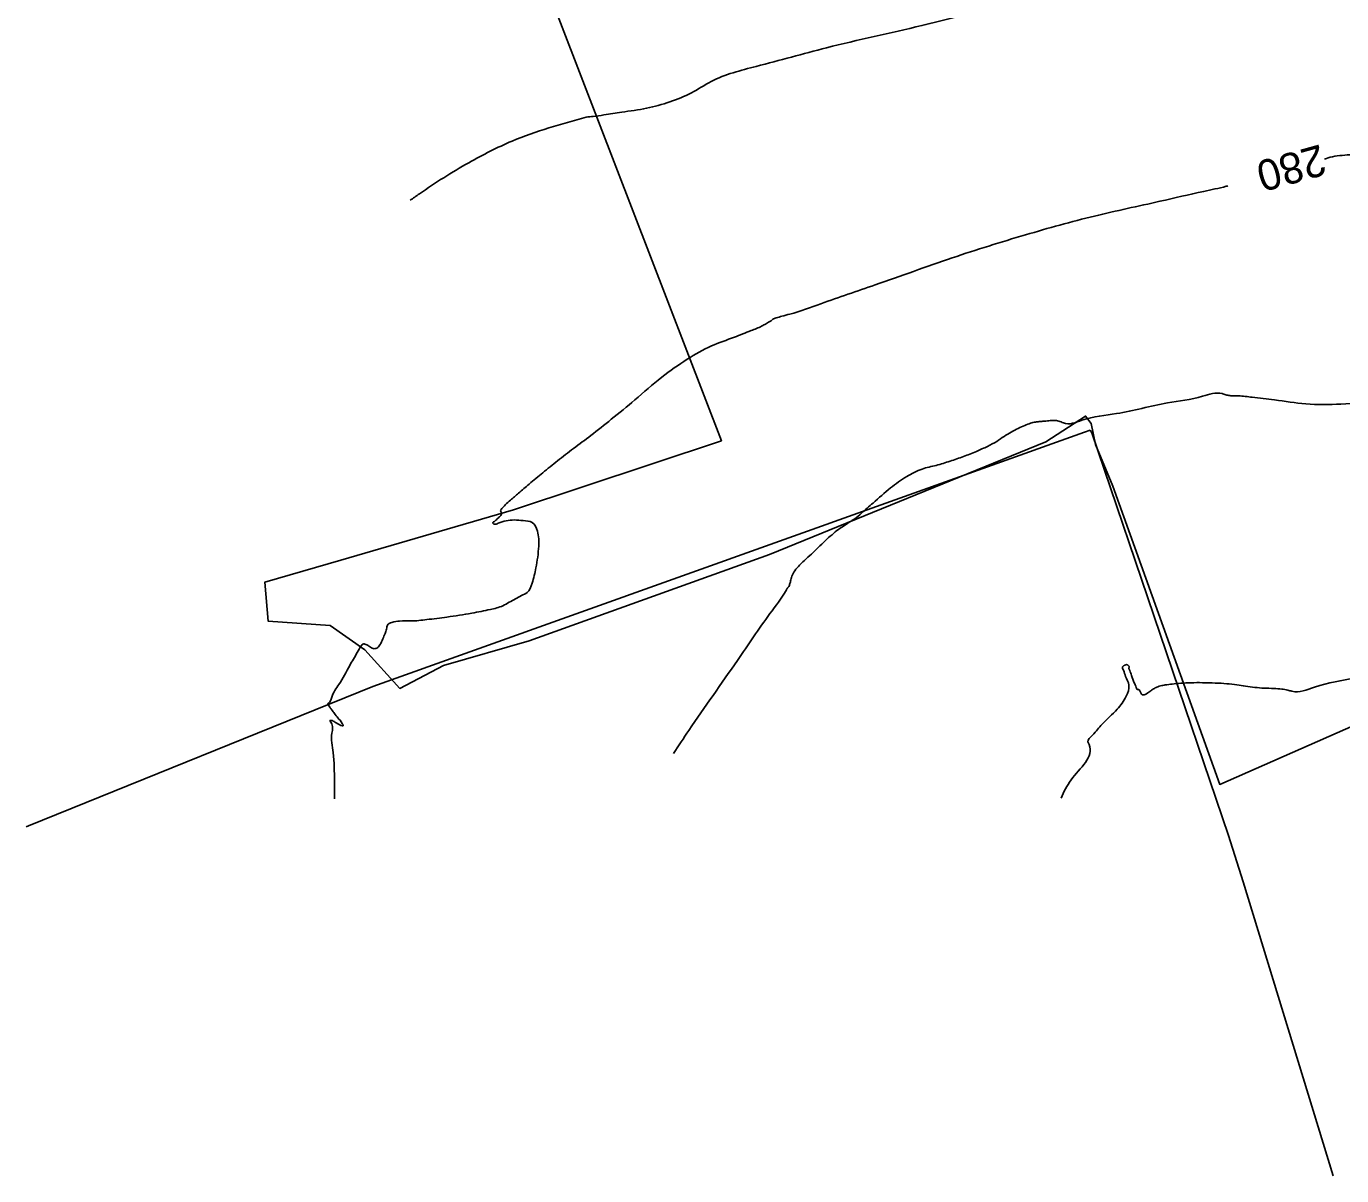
# Model space of a CAD drawing. Extents: x -478464 to -472469, y -1120963 to -1113785.
# Drawn here: x -475889.9 to -475719.4, y -1116153.7 to -1116004.7 of the extents above; entities that cross this region are included whole.
import ezdxf

# ---------------------------------------------------------------- set-up
doc = ezdxf.new("R2010")
doc.units = 0
for name, color, linetype in [('ObPÚ', 7, 'Continuous'), ('VAK_vodovod', 7, 'Continuous'), ('Vrstevnice_hlavni', 7, 'Continuous'), ('Vrstevnice_popis', 7, 'Continuous'), ('Vrstevnice_vedlejsi', 7, 'Continuous')]:
    doc.layers.add(name, color=color, linetype=linetype)

msp = doc.modelspace()

# ---------------------------------------------------------------- linework, layer by layer
at = {"layer": 'ObPÚ'}
msp.add_lwpolyline([(-475822.67, -1115998.95), (-475799.8, -1116058.43), (-475826.72, -1116067.41), (-475849.13, -1116073.91), (-475858.96, -1116076.76), (-475858.53, -1116081.84), (-475850.51, -1116082.37), (-475846.01, -1116085.52), (-475841.49, -1116090.53), (-475835.81, -1116087.59), (-475824.69, -1116084.35), (-475793.58, -1116073.18), (-475757.75, -1116058.57), (-475752.61, -1116055.25), (-475751.89, -1116056.2), (-475751.3, -1116058.92), (-475749.06, -1116064.34), (-475735.22, -1116102.98), (-475699.02, -1116087.04)], dxfattribs=at)
at = {"layer": 'VAK_vodovod'}
for points in [[(-475889.88, -1116108.469), (-475889.59, -1116108.35), (-475844.989, -1116090.309), (-475752.719, -1116057.309), (-475752.027, -1116057.077)], [(-475752.027, -1116057.077), (-475751.789, -1116057.42), (-475734.09, -1116109.6), (-475732.17, -1116115.59), (-475720.526, -1116153.696)]]:
    msp.add_lwpolyline(points, dxfattribs=at)
at = {"layer": 'Vrstevnice_hlavni'}
for points in [[(-475721.656, -1116021.921), (-475720.62, -1116021.633), (-475718.031, -1116021.363), (-475713.372, -1116020.965), (-475706.644, -1116020.44), (-475699.945, -1116019.714), (-475693.277, -1116018.786), (-475686.638, -1116017.656), (-475681.664, -1116016.951), (-475678.354, -1116016.672), (-475676.708, -1116016.818), (-475672.839, -1116016.975), (-475666.748, -1116017.142), (-475658.434, -1116017.321), (-475652.719, -1116017.574), (-475649.603, -1116017.901), (-475649.085, -1116018.302), (-475648.228, -1116018.475), (-475647.031, -1116018.42), (-475645.495, -1116018.137), (-475643.612, -1116018.247), (-475641.384, -1116018.748), (-475638.81, -1116019.641), (-475635.789, -1116020.801), (-475632.319, -1116022.229), (-475628.402, -1116023.923), (-475624.07, -1116026.55), (-475619.323, -1116030.11), (-475614.162, -1116034.601), (-475609.969, -1116038.094), (-475606.743, -1116040.588), (-475604.485, -1116042.082), (-475602.862, -1116043.199), (-475601.875, -1116043.937), (-475601.523, -1116044.296), (-475601.083, -1116044.742), (-475600.556, -1116045.273), (-475599.94, -1116045.889), (-475598.642, -1116047.373), (-475596.662, -1116049.725), (-475594.001, -1116052.945), (-475592.012, -1116055.361), (-475590.694, -1116056.974), (-475590.049, -1116057.784), (-475589.53, -1116058.403), (-475589.136, -1116058.832), (-475588.867, -1116059.071), (-475588.149, -1116059.767), (-475586.98, -1116060.92), (-475585.362, -1116062.531), (-475583.813, -1116064.295), (-475582.333, -1116066.213), (-475580.922, -1116068.285), (-475581.168, -1116072.263)], [(-475734.144, -1116025.39), (-475734.387, -1116025.457), (-475737.287, -1116026.117), (-475742.967, -1116027.402), (-475751.425, -1116029.313), (-475760.397, -1116031.757), (-475769.883, -1116034.735), (-475779.883, -1116038.248), (-475786.895, -1116040.679), (-475790.919, -1116042.028), (-475791.955, -1116042.297), (-475792.697, -1116042.52), (-475793.144, -1116042.699), (-475793.297, -1116042.833), (-475793.588, -1116043.024), (-475794.017, -1116043.273), (-475794.584, -1116043.58), (-475795.952, -1116044.161), (-475798.119, -1116045.015), (-475801.087, -1116046.144), (-475804.225, -1116047.876), (-475807.532, -1116050.21), (-475811.009, -1116053.146), (-475814.071, -1116055.662), (-475816.718, -1116057.758), (-475818.95, -1116059.434), (-475821.025, -1116061.042), (-475822.943, -1116062.582), (-475824.704, -1116064.055), (-475826.102, -1116065.24), (-475827.136, -1116066.137), (-475827.806, -1116066.746), (-475828.232, -1116067.209), (-475828.413, -1116067.526), (-475828.351, -1116067.695), (-475828.313, -1116067.833), (-475828.301, -1116067.938), (-475828.314, -1116068.011), (-475828.374, -1116068.106), (-475828.48, -1116068.222), (-475828.632, -1116068.36), (-475828.838, -1116068.557), (-475829.097, -1116068.811), (-475829.411, -1116069.123), (-475829.283, -1116069.23), (-475828.713, -1116069.131), (-475827.701, -1116068.826), (-475826.629, -1116068.71), (-475825.498, -1116068.782), (-475824.306, -1116069.042), (-475823.632, -1116070.151), (-475823.476, -1116072.107), (-475823.837, -1116074.911), (-475824.33, -1116076.913), (-475824.954, -1116078.115), (-475825.71, -1116078.516), (-475826.49, -1116078.935), (-475827.294, -1116079.372), (-475828.122, -1116079.828), (-475829.743, -1116080.299), (-475832.155, -1116080.784), (-475835.36, -1116081.285), (-475837.985, -1116081.623), (-475840.031, -1116081.798), (-475841.497, -1116081.812), (-475842.513, -1116081.989), (-475843.078, -1116082.332), (-475843.194, -1116082.84), (-475843.394, -1116083.435), (-475843.681, -1116084.119), (-475844.052, -1116084.891), (-475844.462, -1116085.311), (-475844.911, -1116085.379), (-475845.399, -1116085.096), (-475845.763, -1116084.899), (-475846.004, -1116084.788), (-475846.121, -1116084.764), (-475846.236, -1116084.79), (-475846.348, -1116084.866), (-475846.459, -1116084.992), (-475846.998, -1116085.894), (-475847.966, -1116087.573), (-475849.364, -1116090.027), (-475850.298, -1116091.666), (-475850.771, -1116092.488), (-475850.781, -1116092.494), (-475850.786, -1116092.51), (-475850.787, -1116092.538), (-475850.784, -1116092.577), (-475850.701, -1116092.72), (-475850.538, -1116092.969), (-475850.294, -1116093.322), (-475849.947, -1116093.789), (-475849.495, -1116094.37), (-475848.939, -1116095.066), (-475848.819, -1116095.385), (-475849.137, -1116095.329)], [(-475849.137, -1116095.329), (-475849.892, -1116094.896), (-475850.356, -1116094.685), (-475850.529, -1116094.697), (-475850.411, -1116094.93), (-475850.275, -1116096.32), (-475850.122, -1116098.866), (-475849.952, -1116102.567), (-475849.948, -1116104.864)]]:
    msp.add_spline(points, degree=3, dxfattribs=at)
at = {"layer": 'Vrstevnice_vedlejsi'}
for points in [[(-475635.042, -1115991.631), (-475637.589, -1115991.349), (-475640.452, -1115991.123), (-475643.63, -1115990.953), (-475647.123, -1115990.838), (-475652.644, -1115990.705), (-475660.192, -1115990.553), (-475669.769, -1115990.383), (-475679.613, -1115990.46), (-475689.725, -1115990.784), (-475700.106, -1115991.356), (-475708.103, -1115991.646), (-475713.716, -1115991.655), (-475716.946, -1115991.383), (-475719.838, -1115991.391), (-475722.394, -1115991.679), (-475724.612, -1115992.248), (-475729.232, -1115993.416), (-475736.252, -1115995.184), (-475745.674, -1115997.552), (-475752.388, -1115999.252), (-475756.395, -1116000.282), (-475757.696, -1116000.643), (-475758.674, -1116000.909), (-475759.329, -1116001.079), (-475759.662, -1116001.154), (-475760.046, -1116001.261), (-475760.481, -1116001.4), (-475760.966, -1116001.571), (-475765.411, -1116002.645), (-475773.817, -1116004.623), (-475786.183, -1116007.506), (-475795.284, -1116009.921), (-475801.119, -1116011.87), (-475803.69, -1116013.353), (-475806.479, -1116014.511), (-475809.486, -1116015.345), (-475812.713, -1116015.854), (-475815.017, -1116016.208), (-475816.399, -1116016.406), (-475817.32, -1116016.489)], [(-475817.32, -1116016.489), (-475826.925, -1116019.603), (-475832.531, -1116022.398), (-475838.942, -1116026.432), (-475840.138, -1116027.275)], [(-475700.917, -1116051.306), (-475702.197, -1116051.318), (-475704.886, -1116051.643), (-475708.985, -1116052.28), (-475714.492, -1116053.23), (-475719.518, -1116053.691), (-475724.06, -1116053.664), (-475728.121, -1116053.148), (-475731.025, -1116052.804), (-475732.775, -1116052.632), (-475733.368, -1116052.632), (-475733.923, -1116052.581), (-475734.439, -1116052.479), (-475734.917, -1116052.326), (-475737.433, -1116052.681), (-475741.989, -1116053.543), (-475748.583, -1116054.912), (-475753.08, -1116055.776), (-475755.48, -1116056.133), (-475755.782, -1116055.985), (-475756.085, -1116055.883), (-475756.389, -1116055.827), (-475756.695, -1116055.817), (-475757.021, -1116055.823), (-475757.369, -1116055.843), (-475757.738, -1116055.879), (-475758.15, -1116055.919), (-475758.606, -1116055.963), (-475759.106, -1116056.011), (-475759.727, -1116056.173), (-475760.47, -1116056.449), (-475761.333, -1116056.838), (-475762.228, -1116057.313), (-475763.155, -1116057.871), (-475764.112, -1116058.515), (-475765.311, -1116059.165), (-475766.751, -1116059.821), (-475768.433, -1116060.485), (-475770.168, -1116061.086), (-475771.957, -1116061.625), (-475773.799, -1116062.103), (-475775.775, -1116063.076), (-475777.886, -1116064.546), (-475780.13, -1116066.512), (-475781.67, -1116067.847), (-475782.506, -1116068.549), (-475782.636, -1116068.62), (-475782.994, -1116068.848), (-475783.58, -1116069.232), (-475784.394, -1116069.774), (-475785.239, -1116070.426), (-475786.116, -1116071.187), (-475787.025, -1116072.058), (-475787.918, -1116072.909), (-475788.796, -1116073.739), (-475789.657, -1116074.549), (-475790.282, -1116075.298), (-475790.672, -1116075.987), (-475790.825, -1116076.616), (-475790.95, -1116077.06), (-475791.046, -1116077.319), (-475791.114, -1116077.392), (-475791.169, -1116077.452), (-475791.211, -1116077.501), (-475791.24, -1116077.537), (-475791.26, -1116077.563), (-475791.268, -1116077.577), (-475791.267, -1116077.581), (-475791.268, -1116077.585), (-475791.272, -1116077.59), (-475791.278, -1116077.596), (-475791.281, -1116077.6), (-475791.283, -1116077.603), (-475791.283, -1116077.604), (-475791.298, -1116077.632), (-475791.329, -1116077.688), (-475791.375, -1116077.772), (-475793.505, -1116080.848), (-475797.72, -1116086.917), (-475804.02, -1116095.979), (-475806.003, -1116098.98)], [(-475755.762, -1116104.759), (-475754.48, -1116102.382), (-475752.153, -1116097.799), (-475752.287, -1116097.468), (-475751.723, -1116096.597), (-475750.461, -1116095.186), (-475748.503, -1116093.235), (-475747.342, -1116091.55), (-475746.981, -1116090.13), (-475747.419, -1116088.975), (-475747.69, -1116088.18), (-475747.795, -1116087.744), (-475747.733, -1116087.667), (-475747.651, -1116087.598), (-475747.55, -1116087.537), (-475747.429, -1116087.484), (-475747.326, -1116087.459), (-475747.241, -1116087.464), (-475747.174, -1116087.497), (-475747.111, -1116087.538), (-475747.051, -1116087.585), (-475746.995, -1116087.641), (-475746.964, -1116087.705), (-475746.958, -1116087.778), (-475746.979, -1116087.861), (-475746.875, -1116088.226), (-475746.646, -1116088.875), (-475746.293, -1116089.806), (-475746.026, -1116090.414), (-475745.847, -1116090.697), (-475745.754, -1116090.658), (-475745.644, -1116090.741), (-475745.516, -1116090.949), (-475745.372, -1116091.281), (-475745.096, -1116091.372), (-475744.689, -1116091.224), (-475744.152, -1116090.835), (-475743.672, -1116090.537), (-475743.251, -1116090.329), (-475742.889, -1116090.212), (-475742.268, -1116090.095), (-475741.39, -1116089.98), (-475740.254, -1116089.866), (-475738.942, -1116089.804), (-475737.453, -1116089.794), (-475735.788, -1116089.837), (-475734.301, -1116089.93), (-475732.991, -1116090.073), (-475731.858, -1116090.265), (-475730.683, -1116090.409), (-475729.467, -1116090.504), (-475728.208, -1116090.55), (-475727.187, -1116090.633), (-475726.402, -1116090.752), (-475725.855, -1116090.908), (-475722.932, -1116090.381), (-475717.634, -1116089.17), (-475709.961, -1116087.276), (-475703.537, -1116085.778), (-475698.364, -1116084.678), (-475690.519, -1116083.271)]]:
    msp.add_spline(points, degree=3, dxfattribs=at)

# ---------------------------------------------------------------- texts
at = {"layer": 'Vrstevnice_popis'}
msp.add_text(' 280 ', height=4, rotation=195.52286, dxfattribs=at).set_placement((-475720.724, -1116019.587))

doc.saveas('drawing.dxf')
